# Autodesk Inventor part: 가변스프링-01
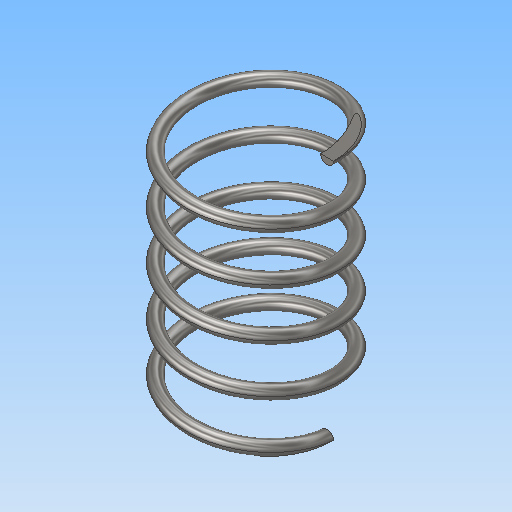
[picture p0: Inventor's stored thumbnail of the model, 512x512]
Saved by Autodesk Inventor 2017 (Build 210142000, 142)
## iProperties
Part Number: 가변스프링-01
Material: 강철, 연강
Document SubType Name: Modeling
Designer: MRC
Density: 7.85 g/cm^3
Appearance: 반연마
Mass: 8.4237 g
Surface Area: 21.7266 cm^2
Volume: 1.07308 cm^3
Author: MRC
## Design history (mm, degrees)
sketch "스케치1"
  geometry: L1 (0, 0)-(0, 37.411); L2 (0, 0)-(11, 0); L3 (0, 37.411)-(11, 37.411); C1 r 1 at (11, 0)
  constraints: 6 end point, 2 horizontal, 1 centre point, 1 coincident, 1 vertical
  dimensions: "d0" = 37.4112 distance of L1.start L1.end (derived); "d1" = 22 diameter of L2.end L1; "d2" = 2 diameter of C1; "d3" = 11 distance of L1.end L3.end
feature "코일1" sketch "스케치1" pitch "d4" = 10; turns "d6" = 5; dims "d5" = 37.4112 (= d0), "d7" = 0, angle "d8" = 90 deg, angle "d9" = 90 deg, "d10" = 0, "d11" = 0
sketch "스케치2"
  geometry: L1 (37.411, 12.5)-(0, 12.5); L2 (0, 12.5)-(0, -12.5); L3 (0, -12.5)-(37.411, -12.5); L4 (37.411, -12.5)-(37.411, 12.5); 2 further points
  constraints: 8 end point, 2 parallel, 1 coincident, 1 horizontal, 1 midpoint, 1 perpendicular
  dimensions: "d12" = 37.4112 distance of L2.end L3.end (= d0); "d13" = 25 distance of L3.end L1.start
extrude "돌출1" sketch "스케치2" stored distance "d14" = 0; taper "d15" = 0 deg
node "솔리드1"
